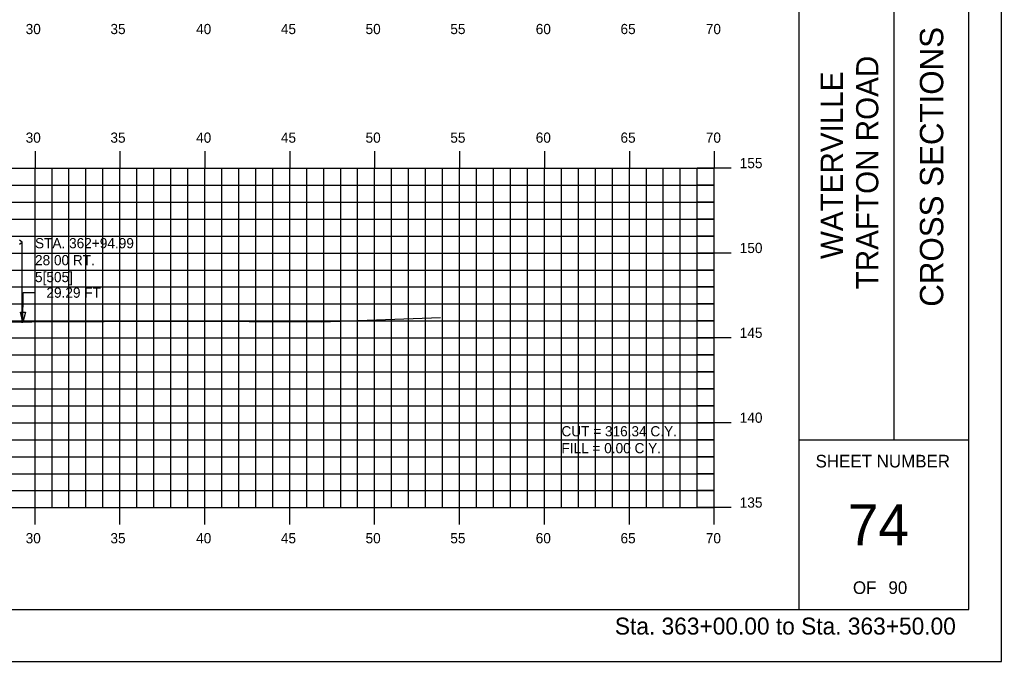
# Model space of a CAD drawing. Extents: x 1146968 to 1147138, y 608981 to 609091.
# Drawn here: x 1147080.3 to 1147138.1, y 608981.3 to 609019.1 of the extents above; entities that cross this region are included whole.
import ezdxf

# ---------------------------------------------------------------- set-up
doc = ezdxf.new("R2010")
doc.units = 0
for name, color, linetype in [('BORDER', 7, 'Continuous'), ('D_Roadway_SubGrade', 7, 'Continuous'), ('D_Text_Standard', 7, 'Continuous'), ('D_Utilities_Pole_Joint_Rt', 7, 'Continuous'), ('H_V ANNOTATION', 7, 'Continuous'), ('HIGHWAY_TITLE', 7, 'Continuous'), ('MAJOR', 7, 'Continuous'), ('MINOR', 7, 'Continuous'), ('PLOT BOUNDARY', 7, 'Continuous'), ('S_Roadway_Centerline', 7, 'Continuous')]:
    doc.layers.add(name, color=color, linetype=linetype)

msp = doc.modelspace()

# ---------------------------------------------------------------- linework, layer by layer
at = {"layer": 'BORDER'}
for p, q in [((1147126.185, 608984.335), (1147126.185, 609089.335)), ((1147131.776, 608994.338), (1147131.776, 609029.338)), ((1147126.185, 608994.338), (1147136.185, 608994.338))]:
    msp.add_line(p, q, dxfattribs=at)
msp.add_lwpolyline([(1146976.185, 608984.335), (1147136.185, 608984.335), (1147136.185, 609089.335), (1146976.185, 609089.335)], close=True, dxfattribs=at)
at = {"layer": 'D_Roadway_SubGrade'}
msp.add_line((1147071.549, 609001.42), (1147080.474, 609001.271), dxfattribs=at)
at = {"layer": 'D_Text_Standard'}
msp.add_lwpolyline([(1147080.474, 609001.271), (1147080.495, 609003.002), (1147081.175, 609003.002)], dxfattribs=at)
msp.add_lwpolyline([(1147080.474, 609001.271), (1147080.336, 609001.854), (1147080.627, 609001.851)], close=True, dxfattribs=at)
at = {"layer": 'D_Utilities_Pole_Joint_Rt'}
for p, q in [((1147080.434, 609005.978), (1147080.278, 609006.088)), ((1147080.278, 609005.867), (1147080.434, 609005.978)), ((1147080.434, 609001.22), (1147080.434, 609005.978))]:
    msp.add_line(p, q, dxfattribs=at)
at = {"layer": 'MAJOR'}
for p, q in [((1147081.184, 609011.337), (1147081.184, 609010.335)), ((1147086.184, 609011.337), (1147086.184, 609010.335)), ((1147091.184, 609011.337), (1147091.184, 609010.335)), ((1147096.184, 609011.337), (1147096.184, 609010.335)), ((1147101.184, 609011.337), (1147101.184, 609010.335)), ((1147106.184, 609011.337), (1147106.184, 609010.335)), ((1147111.184, 609011.337), (1147111.184, 609010.335)), ((1147116.184, 609011.337), (1147116.184, 609010.335)), ((1147121.184, 609011.337), (1147121.184, 609010.335)), ((1146981.184, 609010.335), (1147121.184, 609010.335)), ((1146981.184, 609010.335), (1147121.184, 609010.335)), ((1147081.184, 608990.335), (1147081.184, 609010.335)), ((1147086.184, 608990.335), (1147086.184, 609010.335)), ((1147091.184, 608990.335), (1147091.184, 609010.335)), ((1147096.184, 608990.335), (1147096.184, 609010.335)), ((1147101.184, 608990.335), (1147101.184, 609010.335)), ((1147106.184, 608990.335), (1147106.184, 609010.335)), ((1147111.184, 608990.335), (1147111.184, 609010.335)), ((1147116.184, 608990.335), (1147116.184, 609010.335)), ((1147122.186, 609010.335), (1147120.182, 609010.335)), ((1147121.184, 608990.335), (1147121.184, 609010.335)), ((1147121.184, 608990.335), (1147121.184, 609010.335)), ((1146981.184, 609005.335), (1147121.184, 609005.335)), ((1147122.186, 609005.335), (1147120.182, 609005.335)), ((1146981.184, 609000.335), (1147121.184, 609000.335)), ((1147122.186, 609000.335), (1147120.182, 609000.335)), ((1146981.184, 608995.335), (1147121.184, 608995.335)), ((1147122.186, 608995.335), (1147120.182, 608995.335)), ((1146981.184, 608990.335), (1147121.184, 608990.335)), ((1146981.184, 608990.335), (1147121.184, 608990.335)), ((1147081.184, 608989.333), (1147081.184, 608990.335)), ((1147086.184, 608989.333), (1147086.184, 608990.335)), ((1147091.184, 608989.333), (1147091.184, 608990.335)), ((1147096.184, 608989.333), (1147096.184, 608990.335)), ((1147101.184, 608989.333), (1147101.184, 608990.335)), ((1147106.184, 608989.333), (1147106.184, 608990.335)), ((1147111.184, 608989.333), (1147111.184, 608990.335)), ((1147116.184, 608989.333), (1147116.184, 608990.335)), ((1147122.186, 608990.335), (1147120.182, 608990.335)), ((1147121.184, 608989.333), (1147121.184, 608990.335))]:
    msp.add_line(p, q, dxfattribs=at)
at = {"layer": 'MINOR'}
for p, q in [((1147082.184, 608990.335), (1147082.184, 609010.335)), ((1147083.184, 608990.335), (1147083.184, 609010.335)), ((1147084.184, 608990.335), (1147084.184, 609010.335)), ((1147085.184, 608990.335), (1147085.184, 609010.335)), ((1147087.184, 608990.335), (1147087.184, 609010.335)), ((1147088.184, 608990.335), (1147088.184, 609010.335)), ((1147089.184, 608990.335), (1147089.184, 609010.335)), ((1147090.184, 608990.335), (1147090.184, 609010.335)), ((1147092.184, 608990.335), (1147092.184, 609010.335)), ((1147093.184, 608990.335), (1147093.184, 609010.335)), ((1147094.184, 608990.335), (1147094.184, 609010.335)), ((1147095.184, 608990.335), (1147095.184, 609010.335)), ((1147097.184, 608990.335), (1147097.184, 609010.335)), ((1147098.184, 608990.335), (1147098.184, 609010.335)), ((1147099.184, 608990.335), (1147099.184, 609010.335)), ((1147100.184, 608990.335), (1147100.184, 609010.335)), ((1147102.184, 608990.335), (1147102.184, 609010.335)), ((1147103.184, 608990.335), (1147103.184, 609010.335)), ((1147104.184, 608990.335), (1147104.184, 609010.335)), ((1147105.184, 608990.335), (1147105.184, 609010.335)), ((1147107.184, 608990.335), (1147107.184, 609010.335)), ((1147108.184, 608990.335), (1147108.184, 609010.335)), ((1147109.184, 608990.335), (1147109.184, 609010.335)), ((1147110.184, 608990.335), (1147110.184, 609010.335)), ((1147112.184, 608990.335), (1147112.184, 609010.335)), ((1147113.184, 608990.335), (1147113.184, 609010.335)), ((1147114.184, 608990.335), (1147114.184, 609010.335)), ((1147115.184, 608990.335), (1147115.184, 609010.335)), ((1147117.184, 608990.335), (1147117.184, 609010.335)), ((1147118.184, 608990.335), (1147118.184, 609010.335)), ((1147119.184, 608990.335), (1147119.184, 609010.335)), ((1147120.184, 608990.335), (1147120.184, 609010.335)), ((1146981.184, 609009.335), (1147121.184, 609009.335)), ((1147121.184, 609009.335), (1147120.182, 609009.335)), ((1146981.184, 609008.335), (1147121.184, 609008.335)), ((1147121.184, 609008.335), (1147120.182, 609008.335)), ((1146981.184, 609007.335), (1147121.184, 609007.335)), ((1147121.184, 609007.335), (1147120.182, 609007.335)), ((1146981.184, 609006.335), (1147121.184, 609006.335)), ((1147121.184, 609006.335), (1147120.182, 609006.335)), ((1146981.184, 609004.335), (1147121.184, 609004.335)), ((1147121.184, 609004.335), (1147120.182, 609004.335)), ((1146981.184, 609003.335), (1147121.184, 609003.335)), ((1147121.184, 609003.335), (1147120.182, 609003.335)), ((1146981.184, 609002.335), (1147121.184, 609002.335)), ((1147121.184, 609002.335), (1147120.182, 609002.335)), ((1146981.184, 609001.335), (1147121.184, 609001.335)), ((1147121.184, 609001.335), (1147120.182, 609001.335)), ((1146981.184, 608999.335), (1147121.184, 608999.335)), ((1147121.184, 608999.335), (1147120.182, 608999.335)), ((1146981.184, 608998.335), (1147121.184, 608998.335)), ((1147121.184, 608998.335), (1147120.182, 608998.335)), ((1146981.184, 608997.335), (1147121.184, 608997.335)), ((1147121.184, 608997.335), (1147120.182, 608997.335)), ((1146981.184, 608996.335), (1147121.184, 608996.335)), ((1147121.184, 608996.335), (1147120.182, 608996.335)), ((1146981.184, 608994.335), (1147121.184, 608994.335)), ((1147121.184, 608994.335), (1147120.182, 608994.335)), ((1146981.184, 608993.335), (1147121.184, 608993.335)), ((1147121.184, 608993.335), (1147120.182, 608993.335)), ((1146981.184, 608992.335), (1147121.184, 608992.335)), ((1147121.184, 608992.335), (1147120.182, 608992.335)), ((1146981.184, 608991.335), (1147121.184, 608991.335)), ((1147121.184, 608991.335), (1147120.182, 608991.335))]:
    msp.add_line(p, q, dxfattribs=at)
at = {"layer": 'PLOT BOUNDARY'}
msp.add_lwpolyline([(1146968.091, 608981.276), (1147138.091, 608981.276), (1147138.091, 609091.276), (1146968.091, 609091.276)], close=True, dxfattribs=at)
at = {"layer": 'S_Roadway_Centerline'}
msp.add_lwpolyline([(1147077.117, 609001.224), (1147081.001, 609001.278), (1147089.529, 609001.315), (1147098.057, 609001.286), (1147105.065, 609001.542)], dxfattribs=at)

# ---------------------------------------------------------------- texts
at = {"layer": 'BORDER'}
msp.add_text('CROSS SECTIONS', height=1.37787, rotation=90, dxfattribs=at).set_placement((1147134.669, 609002.172))
for s, height, p in [('SHEET NUMBER', 0.74527, (1147127.15, 608992.701)), ('74', 2.4194, (1147129.046, 608988.118)), ('OF', 0.7453, (1147129.351, 608985.248)), ('90', 0.7453, (1147131.441, 608985.248))]:
    msp.add_text(s, height=height, dxfattribs=at).set_placement(p)
at = {"layer": 'D_Text_Standard'}
for s, p in [('STA. 362+94.99', (1147081.184, 609005.618)), ('28.00 RT.', (1147081.184, 609004.616)), ('5[505] ', (1147081.184, 609003.62)), ('29.29 FT', (1147081.855, 609002.702)), ('CUT = 316.34 C.Y.', (1147112.184, 608994.535)), ('FILL = 0.00 C.Y.', (1147112.184, 608993.539))]:
    msp.add_text(s, height=0.6, dxfattribs=at).set_placement(p)
at = {"layer": 'H_V ANNOTATION'}
for s, height, p in [('30', 0.6, (1147080.633, 609018.235)), ('35', 0.6, (1147085.625, 609018.235)), ('40', 0.6, (1147090.671, 609018.235)), ('45', 0.6, (1147095.662, 609018.235)), ('50', 0.6, (1147100.649, 609018.235)), ('55', 0.6, (1147105.641, 609018.235)), ('60', 0.6, (1147110.671, 609018.235)), ('65', 0.6, (1147115.662, 609018.235)), ('70', 0.6, (1147120.686, 609018.235)), ('30', 0.6, (1147080.633, 609011.835)), ('35', 0.6, (1147085.625, 609011.835)), ('40', 0.6, (1147090.671, 609011.835)), ('45', 0.6, (1147095.662, 609011.835)), ('50', 0.6, (1147100.649, 609011.835)), ('55', 0.6, (1147105.641, 609011.835)), ('60', 0.6, (1147110.671, 609011.835)), ('65', 0.6, (1147115.662, 609011.835)), ('70', 0.6, (1147120.686, 609011.835)), ('155', 0.6, (1147122.684, 609010.335)), ('150', 0.6, (1147122.684, 609005.335)), ('145', 0.6, (1147122.684, 609000.335)), ('140', 0.6, (1147122.684, 608995.335)), ('135', 0.6, (1147122.684, 608990.335)), ('30', 0.6, (1147080.633, 608988.235)), ('35', 0.6, (1147085.625, 608988.235)), ('40', 0.6, (1147090.671, 608988.235)), ('45', 0.6, (1147095.662, 608988.235)), ('50', 0.6, (1147100.649, 608988.235)), ('55', 0.6, (1147105.641, 608988.235)), ('60', 0.6, (1147110.671, 608988.235)), ('65', 0.6, (1147115.662, 608988.235)), ('70', 0.6, (1147120.686, 608988.235)), ('Sta. 363+00.00 to Sta. 363+50.00', 1.0002, (1147115.33, 608982.855))]:
    msp.add_text(s, height=height, dxfattribs=at).set_placement(p)
at = {"layer": 'HIGHWAY_TITLE'}
for s, height, p in [('TRAFTON ROAD', 1.30428, (1147130.844, 609003.201)), ('WATERVILLE', 1.3043, (1147128.757, 609004.98))]:
    msp.add_text(s, height=height, rotation=90, dxfattribs=at).set_placement(p)

doc.saveas('drawing.dxf')
